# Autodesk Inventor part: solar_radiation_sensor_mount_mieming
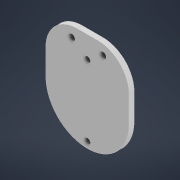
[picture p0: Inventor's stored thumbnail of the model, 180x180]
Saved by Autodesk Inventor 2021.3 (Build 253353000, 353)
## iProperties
Created: 2022-08
Part Number: solar_radiation_sensor_mount_mieming
Material: Generisch
Document SubType Name: Modeling
Designer: markus.rampp
Density: 1 g/cm^3
Appearance: Vorgabe
Author: markus.rampp
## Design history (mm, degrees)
sketch "Skizze1" dims "d20" = 80
  geometry: L1 (-40, 0)-(40, 0); L2 (40, 0)-(40, 55); L3 (40, 55)-(-40, 55); L4 (-40, 55)-(-40, 0); C1 r 2.8 at (0, 34); C2 r 2.8 at (0, -34); C3 r 3 at (-15, 45); C4 r 3 at (15, 45); C5 r 4.5 at (-15, 45); 3 further points
  constraints: 8 end point, 5 centre point, 2 coincident, 2 parallel, 2 vertical, 2 vertical alignment, 1 horizontal, 1 horizontal alignment, 1 perpendicular, 3 other
  dimensions: "d21" = 5.6 diameter of C1; "d22" = 5.6 diameter of C2 (= d21); "d23" = 68 distance of C2.centre C1.centre; "d24" = 34 distance of point (0, 0) C2.centre (= 0.5 x d23); "d37" = 6 diameter of C3; "d38" = 6 diameter of C4; "d39" = 30 distance of C4.centre C3.centre; "d40" = 15 horizontal distance of point (0, 0) C3.centre; "d41" = 9 diameter of C5; "d42" = 45 vertical distance of point (0, 0) C3.centre; "d43" = 10 distance from line of L3 C3.centre
extrude "Extrusion1" new body sketch "Skizze1" distance "d8" = 5; taper "d9" = 0 deg
sketch "Skizze2"
  geometry: L1 (-58, 8)-(58, 8); L2 (58, 8)-(58, -8); L3 (58, -8)-(-58, -8); L4 (-58, -8)-(-58, 8); C1 r 4.5 at (-50, 0); C2 r 4.5 at (50, 0); C3 r 7 at (-50, 0); 1 further point
  constraints: 8 end point, 3 centre point, 2 horizontal alignment, 2 parallel, 1 coincident, 1 horizontal, 1 perpendicular
  dimensions: "d25" = 116 distance of L2.end L3.end; "d26" = 16 distance of L1.end L2.end; "d27" = 8 distance from line of point (0, 0) L1 (= 0.5 x d26); "d28" = 58 distance from line of L2 point (0, 0) (= 0.5 x d25); "d29" = 9 diameter of C1; "d30" = 9 diameter of C2; "d31" = 100 distance of C2.centre C1.centre; "d32" = 50 distance of C2.centre point (0, 0) (= 0.5 x d31); "d33" = 14 diameter of C3
extrude "Extrusion2" join sketch "Skizze2" distance "d34" = 5; taper "d35" = 0 deg
fillet "Rundung3" dims "d36" = 6
fillet "Rundung4" dims "d44" = 30
node "Volumenkörper1"
